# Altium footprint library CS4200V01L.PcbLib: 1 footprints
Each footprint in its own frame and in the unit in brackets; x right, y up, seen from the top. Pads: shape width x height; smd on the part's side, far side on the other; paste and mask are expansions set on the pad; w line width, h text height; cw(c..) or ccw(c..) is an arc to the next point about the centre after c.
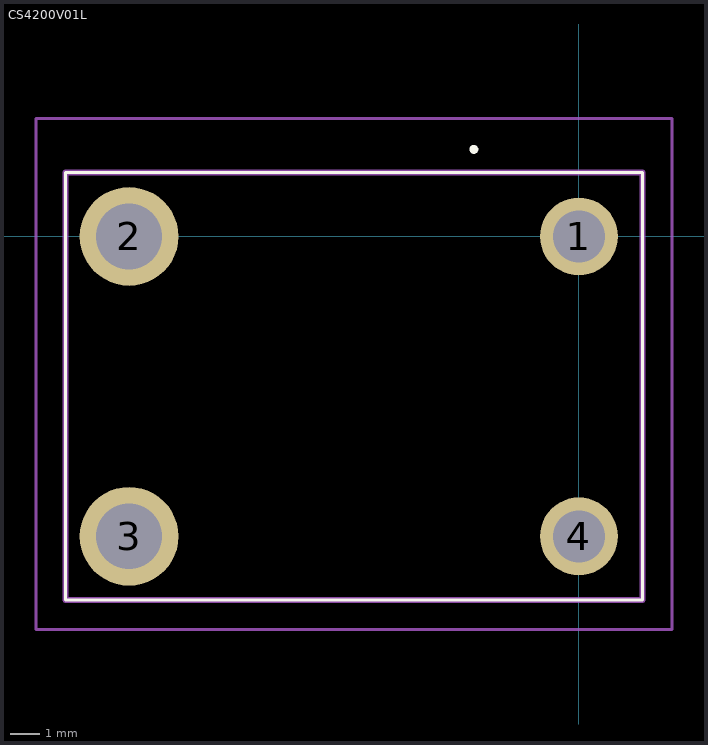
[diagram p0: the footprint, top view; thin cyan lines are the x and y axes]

## CS4200V01L [mm]
pads (4):
  round 2.64 hole 1.76: 1(0,0) 4(0,-10.16)
  round 3.345 hole 2.23: 2(-15.24,0) 3(-15.24,-10.16)
Top Overlay:
  lines w0.1: -17.4,-12.32 2.16,-12.32 2.16,2.16 -17.4,2.16 -17.4,-12.32
  lines w0.2: -3.56,2.9 cw(c-3.56,2.95) -3.56,3 ; -3.56,2.9 -3.56,2.9 ; -3.56,2.9 ccw(c-3.56,2.95) -3.56,3 ; -3.56,2.9 cw(c-3.56,2.95) -3.56,3 ; -3.56,3 -3.56,3 ; -3.56,3 -3.56,3
Mechanical 15:
  lines w0.2: -17.4,-12.32 2.16,-12.32 2.16,2.16 -17.4,2.16 -17.4,-12.32
Mechanical 20:
  lines w0.1: -18.4,-13.32 3.16,-13.32 3.16,4 -18.4,4 -18.4,-13.32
